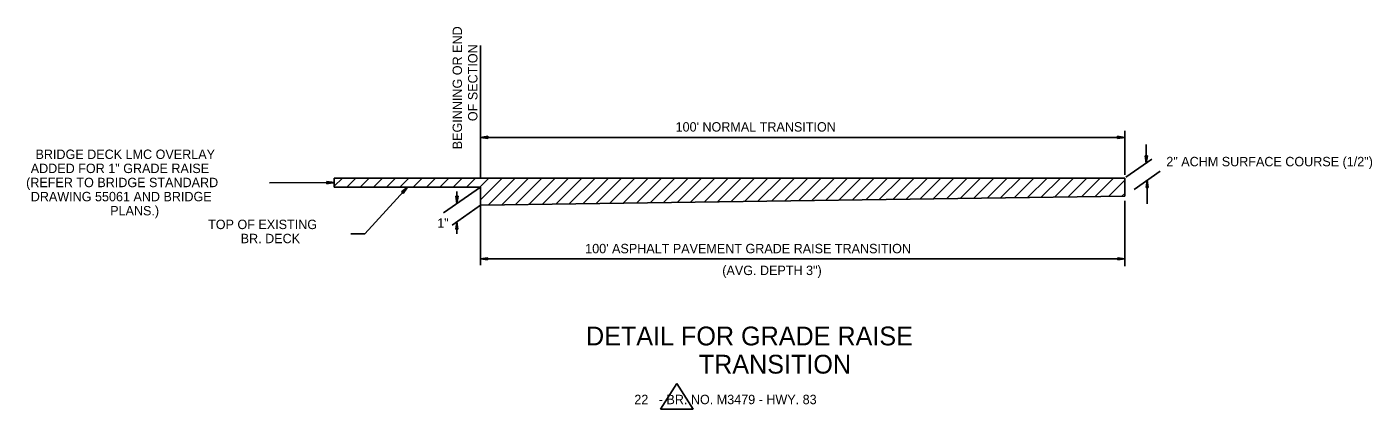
# Model space of a CAD drawing. Extents: x 1929624 to 1935547, y 596315 to 605721.
# Drawn here: x 1931534 to 1932393, y 602682 to 602926 of the extents above; entities that cross this region are included whole.
import ezdxf

# ---------------------------------------------------------------- set-up
doc = ezdxf.new("R2010")
doc.units = 0
for name, color, linetype in [('Default', 7, 'Continuous'), ('R_Border', 7, 'Continuous'), ('R_Draft', 7, 'Continuous')]:
    doc.layers.add(name, color=color, linetype=linetype)

msp = doc.modelspace()

# ---------------------------------------------------------------- linework, layer by layer
at = {"layer": 'Default'}
for p, q in [((1931823.87, 602829.84), (1931823.87, 602914.36)), ((1932235.2, 602831.98), (1932235.2, 602859.98)), ((1931828.54, 602856.49), (1931823.87, 602855.83)), ((1931823.87, 602855.83), (1932235.2, 602855.83)), ((1931828.54, 602855.16), (1931823.87, 602855.83)), ((1931828.54, 602856.27), (1931824.55, 602855.83)), ((1931828.54, 602855.16), (1931824.55, 602855.83)), ((1931828.54, 602856.27), (1931825.44, 602855.83)), ((1931828.54, 602855.38), (1931825.44, 602855.83)), ((1931828.54, 602856.05), (1931826.33, 602855.83)), ((1931828.54, 602855.38), (1931826.33, 602855.83)), ((1931828.54, 602856.05), (1931826.99, 602855.83)), ((1931828.54, 602855.61), (1931826.99, 602855.83)), ((1931828.54, 602855.83), (1931827.88, 602855.83)), ((1931828.54, 602855.61), (1931827.88, 602855.83)), ((1931828.54, 602855.16), (1931828.54, 602856.49)), ((1932230.53, 602856.49), (1932235.2, 602855.83)), ((1932230.53, 602856.49), (1932230.53, 602855.16)), ((1932230.53, 602856.27), (1932233.65, 602855.83)), ((1932230.53, 602856.27), (1932234.3, 602855.83)), ((1932230.53, 602856.05), (1932232.08, 602855.83)), ((1932230.53, 602856.05), (1932232.76, 602855.83)), ((1932230.53, 602855.16), (1932235.2, 602855.83)), ((1932230.53, 602855.61), (1932232.08, 602855.83)), ((1932230.53, 602855.38), (1932233.65, 602855.83)), ((1932230.53, 602855.16), (1932234.3, 602855.83)), ((1932230.53, 602855.38), (1932232.76, 602855.83)), ((1932230.53, 602855.61), (1932231.2, 602855.83)), ((1932230.53, 602855.83), (1932231.2, 602855.83)), ((1932248.96, 602839.41), (1932248.96, 602851.18)), ((1932235.88, 602830.35), (1932252.52, 602841.86)), ((1932248.3, 602844.08), (1932248.96, 602839.41)), ((1932249.63, 602844.08), (1932248.3, 602844.08)), ((1932248.53, 602844.08), (1932248.96, 602840.97)), ((1932248.53, 602844.08), (1932248.96, 602840.31)), ((1932248.74, 602844.08), (1932248.96, 602842.53)), ((1932248.74, 602844.08), (1932248.96, 602841.86)), ((1932249.63, 602844.08), (1932248.96, 602839.41)), ((1932249.18, 602844.08), (1932248.96, 602842.53)), ((1932249.42, 602844.08), (1932248.96, 602840.97)), ((1932249.63, 602844.08), (1932248.96, 602840.31)), ((1932249.42, 602844.08), (1932248.96, 602841.86)), ((1932248.96, 602844.08), (1932248.96, 602843.41)), ((1932249.18, 602844.08), (1932248.96, 602843.41)), ((1932241.31, 602822.65), (1932257.84, 602834.31)), ((1931689.17, 602826.79), (1931730.62, 602826.95)), ((1931725.91, 602826.22), (1931725.96, 602827.63)), ((1931725.91, 602826.22), (1931730.62, 602826.95)), ((1931725.92, 602827.33), (1931729.03, 602826.88)), ((1931725.96, 602827.63), (1931730.62, 602826.95)), ((1931725.96, 602826.53), (1931727.61, 602826.92)), ((1931725.96, 602826.53), (1931728.22, 602826.83)), ((1931726.01, 602826.84), (1931726.8, 602826.89)), ((1931726.01, 602826.84), (1931726.8, 602826.89)), ((1931726.05, 602827.15), (1931727.61, 602826.92)), ((1931726.05, 602827.15), (1931728.22, 602826.83)), ((1931726.09, 602827.46), (1931729.83, 602826.91)), ((1931726.09, 602826.36), (1931729.83, 602826.91)), ((1931726.09, 602826.36), (1931729.03, 602826.88)), ((1931730.62, 602824.06), (1931823.87, 602824.07)), ((1931750.04, 602794.26), (1931777.25, 602824.07)), ((1931773.59, 602821.1), (1931777.25, 602824.07)), ((1931773.78, 602820.86), (1931776.22, 602822.84)), ((1931773.8, 602821.08), (1931776.74, 602823.46)), ((1931774.59, 602820.11), (1931777.25, 602824.07)), ((1931774.61, 602820.33), (1931776.74, 602823.46)), ((1931774.61, 602820.33), (1931776.22, 602822.84)), ((1931800.32, 602807.77), (1931823.87, 602824.07)), ((1931823.87, 602774.21), (1931823.87, 602824.07)), ((1932248.92, 602823.81), (1932249.58, 602828.48)), ((1932248.92, 602823.81), (1932250.25, 602823.81)), ((1932249.14, 602823.81), (1932249.58, 602827.81)), ((1932249.14, 602823.81), (1932249.58, 602826.91)), ((1932249.35, 602823.81), (1932249.58, 602826.25)), ((1932249.35, 602823.81), (1932249.58, 602825.35)), ((1932249.58, 602813.37), (1932249.58, 602828.48)), ((1932250.25, 602823.81), (1932249.58, 602828.48)), ((1932250.25, 602823.81), (1932249.58, 602827.81)), ((1932250.03, 602823.81), (1932249.58, 602826.91)), ((1932250.03, 602823.81), (1932249.58, 602826.25)), ((1932249.8, 602823.81), (1932249.58, 602825.35)), ((1932249.8, 602823.81), (1932249.58, 602824.7)), ((1932249.58, 602823.81), (1932249.58, 602824.7)), ((1931774.59, 602820.11), (1931773.59, 602821.1)), ((1931774.01, 602820.84), (1931775.7, 602822.21)), ((1931774.01, 602820.84), (1931775.23, 602821.83)), ((1931774.21, 602820.6), (1931774.7, 602821.21)), ((1931774.21, 602820.6), (1931774.7, 602821.21)), ((1931774.4, 602820.36), (1931775.7, 602822.21)), ((1931774.4, 602820.36), (1931775.23, 602821.83)), ((1931808.27, 602818.35), (1931808.93, 602813.69)), ((1931809.6, 602818.35), (1931808.27, 602818.35)), ((1931808.49, 602818.35), (1931808.93, 602815.25)), ((1931808.49, 602818.35), (1931808.93, 602814.59)), ((1931808.7, 602818.35), (1931808.93, 602816.81)), ((1931808.7, 602818.35), (1931808.93, 602816.14)), ((1931808.93, 602813.69), (1931808.93, 602821.27)), ((1931809.6, 602818.35), (1931808.93, 602813.69)), ((1931809.15, 602818.35), (1931808.93, 602816.81)), ((1931809.38, 602818.35), (1931808.93, 602815.25)), ((1931809.6, 602818.35), (1931808.93, 602814.59)), ((1931809.38, 602818.35), (1931808.93, 602816.14)), ((1931808.93, 602818.35), (1931808.93, 602817.69)), ((1931809.15, 602818.35), (1931808.93, 602817.69)), ((1932235.2, 602773.59), (1932235.2, 602815.34)), ((1931805.89, 602799.86), (1931823.88, 602812.53)), ((1931808.25, 602797.23), (1931808.91, 602801.9)), ((1931808.25, 602797.23), (1931809.58, 602797.23)), ((1931808.48, 602797.23), (1931808.91, 602801.23)), ((1931808.48, 602797.23), (1931808.91, 602800.34)), ((1931808.68, 602797.23), (1931808.91, 602799.67)), ((1931808.68, 602797.23), (1931808.91, 602798.78)), ((1931809.58, 602797.23), (1931808.91, 602801.9)), ((1931808.91, 602794.35), (1931808.91, 602801.9)), ((1931809.58, 602797.23), (1931808.91, 602801.23)), ((1931809.36, 602797.23), (1931808.91, 602800.34)), ((1931809.36, 602797.23), (1931808.91, 602799.67)), ((1931809.13, 602797.23), (1931808.91, 602798.78)), ((1931809.13, 602797.23), (1931808.91, 602798.13)), ((1931808.91, 602797.23), (1931808.91, 602798.13)), ((1931750.04, 602794.26), (1931741.27, 602794.26)), ((1931828.34, 602779.06), (1931823.87, 602778.41)), ((1932235.2, 602778.41), (1931823.87, 602778.41)), ((1931828.34, 602777.73), (1931823.87, 602778.41)), ((1931828.34, 602779.06), (1931824.55, 602778.41)), ((1931828.34, 602777.96), (1931824.55, 602778.41)), ((1931828.34, 602778.85), (1931825.44, 602778.41)), ((1931828.34, 602777.96), (1931825.44, 602778.41)), ((1931828.34, 602778.85), (1931826.1, 602778.41)), ((1931828.34, 602778.18), (1931826.1, 602778.41)), ((1931828.34, 602778.61), (1931826.99, 602778.41)), ((1931828.34, 602778.18), (1931826.99, 602778.41)), ((1931828.34, 602778.61), (1931827.66, 602778.41)), ((1931828.34, 602778.41), (1931827.66, 602778.41)), ((1931828.34, 602777.73), (1931828.34, 602779.06)), ((1932230.76, 602779.06), (1932235.2, 602778.41)), ((1932230.76, 602779.06), (1932234.53, 602778.41)), ((1932230.76, 602779.06), (1932230.76, 602777.73)), ((1932230.76, 602778.85), (1932233.65, 602778.41)), ((1932230.76, 602778.85), (1932232.99, 602778.41)), ((1932230.76, 602778.61), (1932232.1, 602778.41)), ((1932230.76, 602778.61), (1932231.43, 602778.41)), ((1932230.76, 602777.73), (1932235.2, 602778.41)), ((1932230.76, 602778.18), (1932232.1, 602778.41)), ((1932230.76, 602777.96), (1932233.65, 602778.41)), ((1932230.76, 602777.96), (1932234.53, 602778.41)), ((1932230.76, 602778.18), (1932232.99, 602778.41)), ((1932230.76, 602778.41), (1932231.43, 602778.41))]:
    msp.add_line(p, q, dxfattribs=at)
msp.add_lwpolyline([(1931823.87, 602824.07), (1931823.87, 602824.07)], dxfattribs=at)
at = {"layer": 'R_Border'}
for p, q in [((1931810.01, 602829.84), (1931730.62, 602829.83)), ((1931730.62, 602829.83), (1931730.62, 602824.06)), ((1931730.62, 602824.61), (1931735.85, 602829.83)), ((1931738.56, 602824.06), (1931744.33, 602829.83)), ((1931747.05, 602824.06), (1931752.82, 602829.83)), ((1931755.54, 602824.06), (1931761.31, 602829.83)), ((1931764.02, 602824.07), (1931769.79, 602829.84)), ((1931772.51, 602824.07), (1931778.28, 602829.84)), ((1931780.99, 602824.07), (1931786.76, 602829.84)), ((1931789.48, 602824.07), (1931795.25, 602829.84)), ((1931797.97, 602824.07), (1931803.74, 602829.84)), ((1931806.45, 602824.07), (1931812.22, 602829.84)), ((1931823.87, 602829.84), (1931810.01, 602829.84)), ((1931814.94, 602824.07), (1931820.7, 602829.84)), ((1931823.42, 602824.07), (1931829.19, 602829.84)), ((1932235.2, 602829.88), (1931823.87, 602829.84)), ((1932235.2, 602829.88), (1931823.87, 602829.84)), ((1931823.87, 602824.07), (1931823.87, 602812.53)), ((1931823.87, 602824.07), (1931823.87, 602818.3)), ((1931823.88, 602816.04), (1931837.68, 602829.84)), ((1931828.92, 602812.6), (1931846.16, 602829.84)), ((1931837.53, 602812.72), (1931854.65, 602829.84)), ((1931846.13, 602812.84), (1931863.13, 602829.84)), ((1931854.74, 602812.96), (1931871.62, 602829.84)), ((1931863.35, 602813.08), (1931880.11, 602829.84)), ((1931871.96, 602813.21), (1931888.59, 602829.84)), ((1931880.56, 602813.33), (1931897.08, 602829.84)), ((1931889.17, 602813.45), (1931905.56, 602829.84)), ((1931897.78, 602813.57), (1931914.05, 602829.84)), ((1931906.38, 602813.69), (1931922.54, 602829.85)), ((1931914.99, 602813.81), (1931931.02, 602829.85)), ((1931923.6, 602813.93), (1931939.51, 602829.85)), ((1931932.2, 602814.06), (1931948, 602829.85)), ((1931940.81, 602814.18), (1931956.48, 602829.85)), ((1931949.42, 602814.3), (1931964.97, 602829.85)), ((1931958.02, 602814.42), (1931973.45, 602829.85)), ((1931966.63, 602814.54), (1931981.94, 602829.85)), ((1931975.24, 602814.66), (1931990.43, 602829.85)), ((1931983.84, 602814.79), (1931998.91, 602829.85)), ((1931992.45, 602814.91), (1932007.4, 602829.85)), ((1932001.06, 602815.03), (1932015.88, 602829.85)), ((1932009.67, 602815.15), (1932024.37, 602829.86)), ((1932018.27, 602815.27), (1932032.86, 602829.86)), ((1932026.88, 602815.39), (1932041.34, 602829.86)), ((1932035.49, 602815.51), (1932049.83, 602829.86)), ((1932044.09, 602815.64), (1932058.32, 602829.86)), ((1932052.7, 602815.76), (1932066.8, 602829.86)), ((1932061.31, 602815.88), (1932075.29, 602829.86)), ((1932069.91, 602816), (1932083.77, 602829.86)), ((1932078.52, 602816.12), (1932092.26, 602829.86)), ((1932087.13, 602816.24), (1932100.75, 602829.86)), ((1932095.73, 602816.37), (1932109.23, 602829.86)), ((1932104.34, 602816.49), (1932117.72, 602829.87)), ((1932112.95, 602816.61), (1932126.2, 602829.87)), ((1932121.55, 602816.73), (1932134.69, 602829.87)), ((1932130.16, 602816.85), (1932143.18, 602829.87)), ((1932138.77, 602816.97), (1932151.66, 602829.87)), ((1932147.37, 602817.1), (1932160.15, 602829.87)), ((1932155.98, 602817.22), (1932168.63, 602829.87)), ((1932164.59, 602817.34), (1932177.12, 602829.87)), ((1932173.2, 602817.46), (1932185.61, 602829.87)), ((1932181.8, 602817.58), (1932194.09, 602829.87)), ((1932190.41, 602817.7), (1932202.58, 602829.87)), ((1932199.02, 602817.82), (1932211.07, 602829.87)), ((1932207.62, 602817.95), (1932219.55, 602829.88)), ((1932216.23, 602818.07), (1932228.04, 602829.88)), ((1932224.84, 602818.19), (1932235.2, 602828.56)), ((1932235.22, 602818.34), (1932235.2, 602829.88)), ((1932235.22, 602818.34), (1932235.2, 602829.88)), ((1932235.22, 602818.34), (1932235.2, 602829.88)), ((1931823.87, 602812.53), (1932235.22, 602818.34)), ((1931823.87, 602812.53), (1932235.22, 602818.34)), ((1932233.44, 602818.31), (1932235.21, 602820.08)), ((1931949.26, 602698.67), (1931938.91, 602682.45)), ((1931959.61, 602682.45), (1931949.26, 602698.67)), ((1931938.91, 602682.45), (1931959.61, 602682.45))]:
    msp.add_line(p, q, dxfattribs=at)
msp.add_lwpolyline([(1931730.62, 602824.06), (1931823.87, 602824.07)], dxfattribs=at)

# ---------------------------------------------------------------- texts
at = {"layer": 'Default'}
for s, height, rotation, p in [('BEGINNING OR END', 6, 90, (1931812.14, 602848.22)), ('OF SECTION', 6, 90, (1931822, 602866.17)), ("100' NORMAL TRANSITION ", 6, 360, (1931948.48, 602859.52)), ('BRIDGE DECK LMC OVERLAY ', 6, 360, (1931539.88, 602842.04)), ('ADDED FOR 1" GRADE RAISE', 6, 360, (1931536.85, 602833.04)), ('(REFER TO BRIDGE STANDARD', 6, 360, (1931533.9, 602824.04)), ('DRAWING 55061 AND BRIDGE', 6, 360, (1931536.86, 602815.04)), (' PLANS.)', 6, 360, (1931585.33, 602806.04)), ('TOP OF EXISTING ', 6, 360, (1931650.08, 602797.29)), ('1"', 6, 360, (1931796.33, 602798.13)), ('BR. DECK', 6, 360, (1931670.87, 602788.29)), ("100' ASPHALT PAVEMENT GRADE RAISE TRANSITION", 6, 360, (1931890.78, 602781.87)), ('(AVG. DEPTH 3")', 6, 360, (1931978.27, 602767.96)), ('DETAIL FOR GRADE RAISE', 12, 360, (1931891.31, 602723.09)), ('TRANSITION', 12, 360, (1931963.29, 602705.09))]:
    msp.add_text(s, height=height, rotation=rotation, dxfattribs=at).set_placement(p)
msp.add_text('2" ACHM SURFACE COURSE (1/2")', height=6, dxfattribs=at).set_placement((1932261.73, 602837.38))
at = {"layer": 'R_Draft'}
msp.add_text('      22   - BR. NO. M3479 - HWY. 83', height=6, dxfattribs=at).set_placement((1931908.77, 602685.57))

doc.saveas('drawing.dxf')
